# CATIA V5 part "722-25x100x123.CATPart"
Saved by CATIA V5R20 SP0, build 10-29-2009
Part number: 722-25x100x123
Definition: NONE
Nomenclature: 722-25x100x123
Source: Unknown
Description: 722-25x100x123
Bounding box of the stored display mesh (mm): x -12.5 to 12.5, y -12.5 to 12.5, z -88 to 35
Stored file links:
  C:\Users\Utente\Desktop\IO LAVORO\3D X SITO CF\X SITO\722\722-25x100x123.CATPart
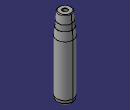
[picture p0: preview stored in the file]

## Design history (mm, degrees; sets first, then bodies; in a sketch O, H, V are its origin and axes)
Body1 "722-25x100x123" (main body)
  Solid1: solid without history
